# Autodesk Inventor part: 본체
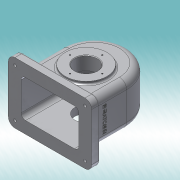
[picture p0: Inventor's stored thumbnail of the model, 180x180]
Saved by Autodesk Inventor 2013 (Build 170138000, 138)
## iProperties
Created: 2016-10
Part Number: 본체
Material: 알루미늄 6061
Document SubType Name: Modeling
Designer: dgall
Density: 2.71 g/cm^3
Mass: 1165.05 g
Surface Area: 1200 cm^2
Volume: 429.909 cm^3
Author: dgall
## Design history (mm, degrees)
sketch "스케치1"
  geometry: L1 (-58, 0)-(-58, -80); L2 (58, 0)-(58, -80); L3 (58, -80)-(-58, -80); A1 r 58 centre (0, 0) between (58, 0) and (-58, 0); 1 further point
  constraints: 6 end point, 2 point on circle, 2 tangent, 1 centre point, 1 coincident, 1 parallel, 1 perpendicular, 1 vertical
  dimensions: "d0" = 116 diameter of A1; "d2" = 80 distance of L1.start L1.end
extrude "돌출1" new body sketch "스케치1" distance "d3" = 77; taper "d4" = 0 deg
node "작업 평면2"
sketch "스케치3"
  geometry: L1 (58, 0)-(58, -80) reference; L2 (58, -80)-(-58, -80) reference; L3 (-58, -80)-(-58, 0) reference; L4 (-52, 0)-(-52, -80); L5 (52, 0)-(52, -80); A1 r 52 centre (0, 0) between (52, 0) and (-52, 0); A2 r 58 centre (0, 0) between (58, 0) and (-58, 0) reference; 1 further point
  constraints: 4 end point, 2 perpendicular, 2 point on circle, 2 point on line, 2 tangent, 1 centre point, 1 coincident
  dimensions: "d11" = 104 diameter of A1
extrude "돌출3" cut sketch "스케치3" distance "d13" = 67; taper "d14" = 0 deg
sketch "스케치4"
  geometry: L1 (-58, -80)-(58, -80) reference; C1 r 37.5 at (0, -15); A1 r 58 centre (0, 0) between (58, 0) and (-58, 0) reference
  constraints: 1 centre point, 1 vertical alignment
  dimensions: "d15" = 75 diameter of C1; "d17" = 65 distance from line of C1.centre L1
extrude "돌출4" join sketch "스케치4" distance "d18" = 5; taper "d19" = 0 deg
sketch "스케치5"
  geometry: L1 (-58, -80)-(58, -80) reference; C1 r 31 at (0, -15); A1 r 58 centre (0, 0) between (58, 0) and (-58, 0) reference
  constraints: 1 centre point, 1 vertical alignment
  dimensions: "d20" = 62 diameter of C1; "d22" = 65 distance from line of L1 C1.centre
extrude "돌출5" join sketch "스케치5" distance "d23" = 10; taper "d24" = 0 deg
sketch "스케치6"
  geometry: C1 r 31 at (0, 0) reference; C2 r 20 at (0, 0); 1 further point
  constraints: 1 centre point, 1 coincident
  dimensions: "d25" = 40 diameter of C2
extrude "돌출6" cut sketch "스케치6" stored distance "d27" = 10; taper "d28" = 0 deg
sketch "스케치7"
  geometry: L1 (-35, 82)-(5, 82) reference; L2 (5, -10)-(-35, -10) reference; L3 (-15, 82)-(-15, -10); L4 (5, 58)-(13, 58); L5 (52, 72)-(0, 72) reference; L6 (13, 58)-(24.747, 72); L7 (5, 72)-(5, 82) reference; L8 (5, 58)-(5, 72); L9 (24.747, 72)-(5, 72); 1 further point
  constraints: 10 end point, 2 collinear, 2 midpoint, 1 perpendicular, 1 point on line, 1 vertical alignment
  dimensions: "d29" = 24 distance of L4.start L1.end; "d30" = 50 deg angle of L4 L6; "d31" = 56 diameter of L4.end L3
revolve "회전1" sketch "스케치7" stored, may be unused: angle "d32" = 90 deg
sketch "스케치8"
  geometry: C1 r 20 at (0, 0) reference; 2 further points
  constraints: 1 vertical alignment
  dimensions: "d33" = 29 distance of C1.centre point (0, 29)
hole "구멍1" sketch "스케치8" at (0, 29) diameter "d34" = 2.459; stored, may be unused: countersink angle "d38" = 90 deg, drill point angle "d40" = 118 deg; dims "d35" = 6, "d36" = 4, "d37" = 2, "d39" = 8
sketch "스케치9"
  geometry: C1 r 20 at (0, 0) reference; 2 further points
  constraints: 1 vertical alignment
  dimensions: "d44" = 26 distance of C1.centre point (0, 26)
hole "구멍2" sketch "스케치9" at (0, 26) diameter "d45" = 2.459; stored, may be unused: countersink angle "d49" = 90 deg, drill point angle "d51" = 118 deg; dims "d46" = 6, "d47" = 4, "d48" = 2, "d50" = 8
sketch "스케치10"
  geometry: L1 (116, 0)-(0, 0) reference; L2 (116, 0)-(116, 77) reference; L3 (0, 77)-(116, 77) reference; L4 (0, 0)-(0, 77) reference; L5 (-17, 93.5)-(133, 93.5); L6 (133, 93.5)-(133, -16.5); L7 (133, -16.5)-(-17, -16.5); L8 (-17, -16.5)-(-17, 93.5); 5 further points
  constraints: 8 end point, 4 midpoint, 2 parallel, 1 horizontal, 1 horizontal alignment, 1 perpendicular, 1 vertical alignment
  dimensions: "d55" = 150 distance of L5.start L5.end; "d57" = 110 distance of L7.end L5.start
extrude "돌출7" join sketch "스케치10" distance "d58" = 15; taper "d59" = 0 deg
node "작업 평면3"
sketch "스케치11"
  geometry: L1 (-150, 0)-(-150, -110) reference; L2 (-150, -110)-(0, -110) reference; L3 (0, 0)-(-150, 0) reference; L4 (0, -110)-(0, 0) reference; C1 r 6 at (-75, -55); 1 further point
  constraints: 1 centre point
  dimensions: "d61" = 12 diameter of C1; "d63" = 55 distance from line of C1.centre L2; "d64" = 75 distance from line of L1 C1.centre
extrude "돌출8" join sketch "스케치11" stored distance "d65" = 15; taper "d66" = 0 deg
sketch "스케치12"
  geometry: L1 (64, 44.5)-(64, 32.5) reference; L2 (64, 44.5)-(58, 44.5) reference; L3 (64, 44.5)-(52, 46.616); L4 (58, 0)-(58, 77) reference; L5 (52, 5)-(52, 72) reference; L6 (52, 46.616)-(52, 38.5); L7 (64, 44.5)-(64, 38.5); L8 (64, 38.5)-(52, 38.5); 1 further point
  constraints: 8 end point, 2 midpoint, 1 collinear, 1 perpendicular, 1 point on line
  dimensions: "d68" = 100 deg angle of L4 L3
revolve "회전2" sketch "스케치12" stored, may be unused: angle "d69" = 90 deg
sketch "스케치13"
  geometry: C1 r 6 at (0, 0) reference; 1 further point
hole "구멍3" sketch "스케치13" at (0, 0) diameter "d70" = 4.459; stored, may be unused: countersink angle "d74" = 90 deg, drill point angle "d76" = 118 deg; dims "d71" = 6, "d72" = 4, "d73" = 2, "d75" = 8
chamfer "모따기1" distance "d77" = 1; stored, may be unused: second distance "d78" = 2, angle "d79" = 45 deg
fillet "모깎기1" dims "d80" = 13
fillet "모깎기2" dims "d81" = 12
sketch "스케치14"
  geometry: A1 r 12 centre (-5, -81.5) between (-17, -81.5) and (-5, -93.5) reference; A2 r 12 centre (121, -81.5) between (121, -93.5) and (133, -81.5) reference; A3 r 12 centre (121, 4.5) between (133, 4.5) and (121, 16.5) reference; A4 r 12 centre (-5, 4.5) between (-5, 16.5) and (-17, 4.5) reference; 1 further point
hole "구멍4" sketch "스케치14" at (-5, -81.5), (121, -81.5), (-5, 4.5), (121, 4.5) diameter "d82" = 5; stored, may be unused: countersink angle "d86" = 90 deg, drill point angle "d88" = 118 deg; dims "d83" = 6, "d84" = 12, "d85" = 5, "d87" = 8
fillet "모깎기3" dims "d89" = 8
fillet "모깎기4" dims "d90" = 3
fillet "모깎기5" dims "d91" = 3
fillet "모깎기6" dims "d92" = 3
sketch "스케치15"
  geometry: L1 (-17.5, -80)-(68.5, -80) reference; L2 (-13, 0)-(-13, -62) reference; 2 further points
  constraints: 1 other
  dimensions: "d93" = 40 distance from line of L1 point (25.5, -40); "d94" = 38.5 distance from line of L2 point (25.5, -40)
feature "엠보싱1" sketch "스케치15" dims "d0" = 116, "d2" = 80, "d95" = 0.5, "d96" = 0
node "솔리드1"
pattern_circular "원형 패턴1" dims angle "d42" = 360 deg
pattern_circular "원형 패턴2" dims angle "d53" = 360 deg
node "절단 모서리 투영2"
other parameters: "d10" = 5, "d60" = -144
